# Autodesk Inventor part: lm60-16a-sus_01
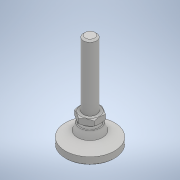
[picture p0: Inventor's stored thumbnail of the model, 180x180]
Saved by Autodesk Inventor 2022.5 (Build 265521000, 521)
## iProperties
Part Number: lm60-16a-sus_01
Material: 一般
Document SubType Name: Modeling
Designer: ImaoCorp
Density: 1 g/cm^3
Appearance: 既定
Author: ImaoCorp
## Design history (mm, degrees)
feature "lm60-16a-sus_01"
node "ソリッド1"
